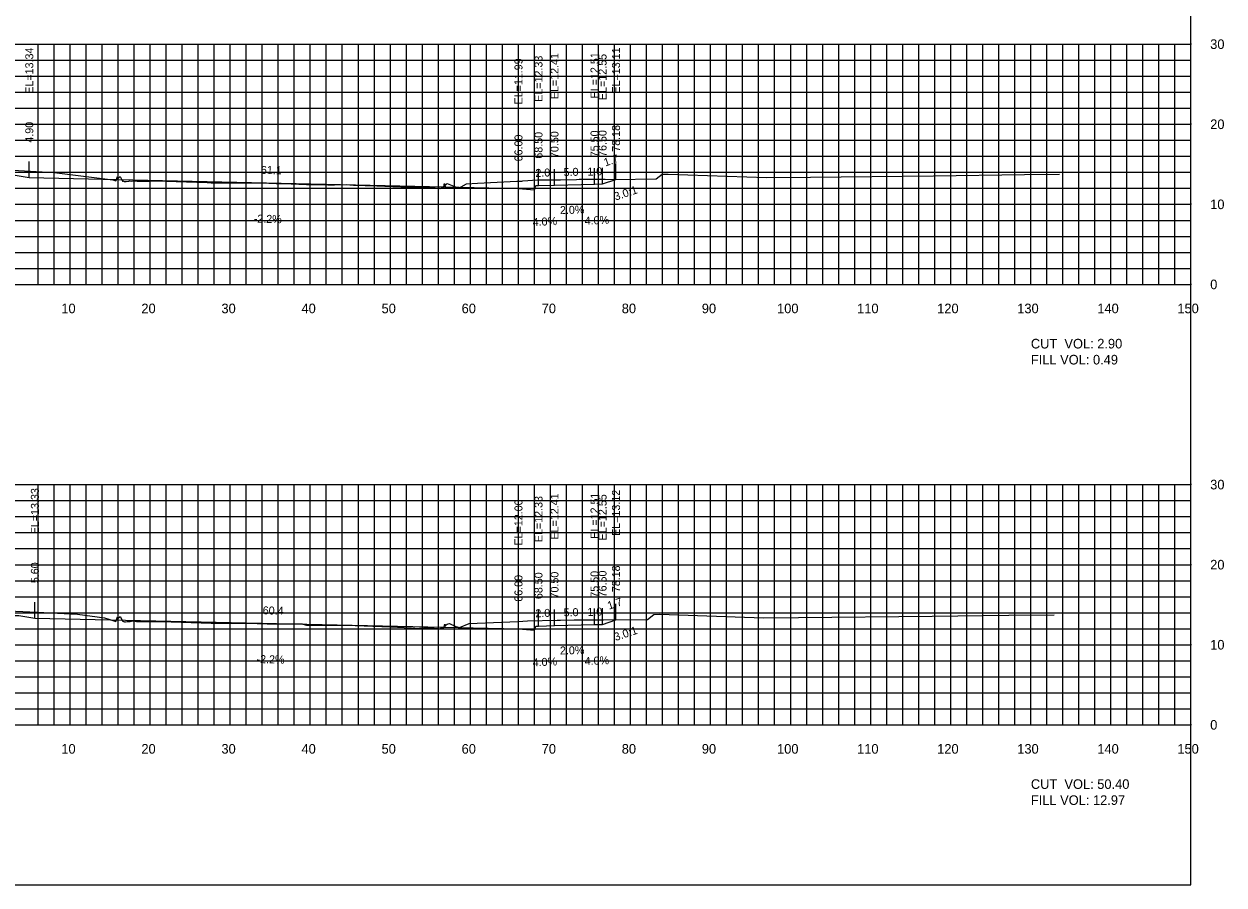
# Model space of a CAD drawing. Extents: x 1797419 to 1809236, y 248759 to 251512.
# Drawn here: x 1802635.2 to 1802785.1, y 250854.9 to 250962.4 of the extents above; entities that cross this region are included whole.
import ezdxf

# ---------------------------------------------------------------- set-up
doc = ezdxf.new("R2010")
doc.units = 0
for name, color, linetype in [('10', 7, 'Continuous'), ('3', 7, 'Continuous'), ('31', 7, 'Continuous'), ('4', 7, 'Continuous'), ('60', 7, 'Continuous'), ('ANNO-TXT', 7, 'Continuous'), ('CL-CNST', 7, 'Continuous'), ('Level 62', 7, 'Continuous'), ('M-ROADS', 7, 'Continuous')]:
    doc.layers.add(name, color=color, linetype=linetype)

msp = doc.modelspace()

# ---------------------------------------------------------------- linework, layer by layer
for p, q in [((1802635.9, 250943.23), (1802635.9, 250945.23)), ((1802697, 250941.88), (1802697, 250943.88)), ((1802699.5, 250942.22), (1802699.5, 250944.22)), ((1802701.5, 250942.3), (1802701.5, 250944.3)), ((1802706.5, 250942.4), (1802706.5, 250944.4)), ((1802707.5, 250942.44), (1802707.5, 250944.44)), ((1802709.18, 250943), (1802709.18, 250945)), ((1802636.6, 250888.22), (1802636.6, 250890.22)), ((1802709.18, 250888.01), (1802709.18, 250890.01)), ((1802697, 250886.89), (1802697, 250888.89)), ((1802699.5, 250887.22), (1802699.5, 250889.22)), ((1802701.5, 250887.3), (1802701.5, 250889.3)), ((1802706.5, 250887.4), (1802706.5, 250889.4)), ((1802707.5, 250887.44), (1802707.5, 250889.44))]:
    msp.add_line(p, q)
msp.add_lwpolyline([(1802481, 250854.89), (1802781, 250854.89), (1802781, 251044.89), (1802481, 251044.89)], close=True)
at = {"layer": '60'}
for p, q in [((1802781, 250929.89), (1802781, 250959.89)), ((1802781.06, 250959.89), (1802781, 250959.89)), ((1802781.06, 250949.89), (1802781, 250949.89)), ((1802781.06, 250939.89), (1802781, 250939.89)), ((1802481, 250929.89), (1802781, 250929.89)), ((1802641, 250929.83), (1802641, 250929.89)), ((1802651, 250929.83), (1802651, 250929.89)), ((1802661, 250929.83), (1802661, 250929.89)), ((1802671, 250929.83), (1802671, 250929.89)), ((1802681, 250929.83), (1802681, 250929.89)), ((1802691, 250929.83), (1802691, 250929.89)), ((1802701, 250929.83), (1802701, 250929.89)), ((1802711, 250929.83), (1802711, 250929.89)), ((1802721, 250929.83), (1802721, 250929.89)), ((1802731, 250929.83), (1802731, 250929.89)), ((1802741, 250929.83), (1802741, 250929.89)), ((1802751, 250929.83), (1802751, 250929.89)), ((1802761, 250929.83), (1802761, 250929.89)), ((1802771, 250929.83), (1802771, 250929.89)), ((1802781, 250929.83), (1802781, 250929.89)), ((1802781.06, 250929.89), (1802781, 250929.89)), ((1802781, 250874.89), (1802781, 250904.89)), ((1802781.06, 250904.89), (1802781, 250904.89)), ((1802781.06, 250894.89), (1802781, 250894.89)), ((1802781.06, 250884.89), (1802781, 250884.89)), ((1802481, 250874.89), (1802781, 250874.89)), ((1802641, 250874.83), (1802641, 250874.89)), ((1802651, 250874.83), (1802651, 250874.89)), ((1802661, 250874.83), (1802661, 250874.89)), ((1802671, 250874.83), (1802671, 250874.89)), ((1802681, 250874.83), (1802681, 250874.89)), ((1802691, 250874.83), (1802691, 250874.89)), ((1802701, 250874.83), (1802701, 250874.89)), ((1802711, 250874.83), (1802711, 250874.89)), ((1802721, 250874.83), (1802721, 250874.89)), ((1802731, 250874.83), (1802731, 250874.89)), ((1802741, 250874.83), (1802741, 250874.89)), ((1802751, 250874.83), (1802751, 250874.89)), ((1802761, 250874.83), (1802761, 250874.89)), ((1802771, 250874.83), (1802771, 250874.89)), ((1802781, 250874.83), (1802781, 250874.89)), ((1802781.06, 250874.89), (1802781, 250874.89))]:
    msp.add_line(p, q, dxfattribs=at)
at = {"layer": 'CL-CNST'}
for points in [[(1802563.49, 250943.08), (1802564.5, 250942.74), (1802565.5, 250942.7), (1802572.5, 250942.56), (1802574.5, 250942.48), (1802574.83, 250942.48), (1802575, 250941.98), (1802577, 250942.15), (1802621.76, 250943.13), (1802623.76, 250943.47), (1802624.26, 250943.47), (1802631, 250943.74), (1802633.4, 250943.57), (1802633.9, 250943.57), (1802635.9, 250943.23), (1802697, 250941.88), (1802699, 250941.72), (1802699.17, 250942.22), (1802699.5, 250942.22), (1802701.5, 250942.3), (1802706.5, 250942.4), (1802707.5, 250942.44), (1802709.18, 250943)], [(1802563.47, 250888.09), (1802564.5, 250887.75), (1802565.5, 250887.71), (1802572.5, 250887.57), (1802574.5, 250887.49), (1802574.83, 250887.49), (1802575, 250886.99), (1802577, 250887.15), (1802621.13, 250888.12), (1802623.13, 250888.46), (1802623.63, 250888.46), (1802631, 250888.76), (1802634.1, 250888.56), (1802634.6, 250888.56), (1802636.6, 250888.22), (1802697, 250886.89), (1802699, 250886.72), (1802699.17, 250887.22), (1802699.5, 250887.22), (1802701.5, 250887.3), (1802706.5, 250887.4), (1802707.5, 250887.44), (1802709.18, 250888.01)]]:
    msp.add_lwpolyline(points, dxfattribs=at)
at = {"layer": 'Level 62'}
for p, q in [((1802481, 250959.89), (1802781, 250959.89)), ((1802637, 250929.89), (1802637, 250959.89)), ((1802639, 250929.89), (1802639, 250959.89)), ((1802641, 250929.89), (1802641, 250959.89)), ((1802643, 250929.89), (1802643, 250959.89)), ((1802645, 250929.89), (1802645, 250959.89)), ((1802647, 250929.89), (1802647, 250959.89)), ((1802649, 250929.89), (1802649, 250959.89)), ((1802651, 250929.89), (1802651, 250959.89)), ((1802653, 250929.89), (1802653, 250959.89)), ((1802655, 250929.89), (1802655, 250959.89)), ((1802657, 250929.89), (1802657, 250959.89)), ((1802659, 250929.89), (1802659, 250959.89)), ((1802661, 250929.89), (1802661, 250959.89)), ((1802663, 250929.89), (1802663, 250959.89)), ((1802665, 250929.89), (1802665, 250959.89)), ((1802667, 250929.89), (1802667, 250959.89)), ((1802669, 250929.89), (1802669, 250959.89)), ((1802671, 250929.89), (1802671, 250959.89)), ((1802673, 250929.89), (1802673, 250959.89)), ((1802675, 250929.89), (1802675, 250959.89)), ((1802677, 250929.89), (1802677, 250959.89)), ((1802679, 250929.89), (1802679, 250959.89)), ((1802681, 250929.89), (1802681, 250959.89)), ((1802683, 250929.89), (1802683, 250959.89)), ((1802685, 250929.89), (1802685, 250959.89)), ((1802687, 250929.89), (1802687, 250959.89)), ((1802689, 250929.89), (1802689, 250959.89)), ((1802691, 250929.89), (1802691, 250959.89)), ((1802693, 250929.89), (1802693, 250959.89)), ((1802695, 250929.89), (1802695, 250959.89)), ((1802697, 250929.89), (1802697, 250959.89)), ((1802699, 250929.89), (1802699, 250959.89)), ((1802701, 250929.89), (1802701, 250959.89)), ((1802703, 250929.89), (1802703, 250959.89)), ((1802705, 250929.89), (1802705, 250959.89)), ((1802707, 250929.89), (1802707, 250959.89)), ((1802709, 250929.89), (1802709, 250959.89)), ((1802711, 250929.89), (1802711, 250959.89)), ((1802713, 250929.89), (1802713, 250959.89)), ((1802715, 250929.89), (1802715, 250959.89)), ((1802717, 250929.89), (1802717, 250959.89)), ((1802719, 250929.89), (1802719, 250959.89)), ((1802721, 250929.89), (1802721, 250959.89)), ((1802723, 250929.89), (1802723, 250959.89)), ((1802725, 250929.89), (1802725, 250959.89)), ((1802727, 250929.89), (1802727, 250959.89)), ((1802729, 250929.89), (1802729, 250959.89)), ((1802731, 250929.89), (1802731, 250959.89)), ((1802733, 250929.89), (1802733, 250959.89)), ((1802735, 250929.89), (1802735, 250959.89)), ((1802737, 250929.89), (1802737, 250959.89)), ((1802739, 250929.89), (1802739, 250959.89)), ((1802741, 250929.89), (1802741, 250959.89)), ((1802743, 250929.89), (1802743, 250959.89)), ((1802745, 250929.89), (1802745, 250959.89)), ((1802747, 250929.89), (1802747, 250959.89)), ((1802749, 250929.89), (1802749, 250959.89)), ((1802751, 250929.89), (1802751, 250959.89)), ((1802753, 250929.89), (1802753, 250959.89)), ((1802755, 250929.89), (1802755, 250959.89)), ((1802757, 250929.89), (1802757, 250959.89)), ((1802759, 250929.89), (1802759, 250959.89)), ((1802761, 250929.89), (1802761, 250959.89)), ((1802763, 250929.89), (1802763, 250959.89)), ((1802765, 250929.89), (1802765, 250959.89)), ((1802767, 250929.89), (1802767, 250959.89)), ((1802769, 250929.89), (1802769, 250959.89)), ((1802771, 250929.89), (1802771, 250959.89)), ((1802773, 250929.89), (1802773, 250959.89)), ((1802775, 250929.89), (1802775, 250959.89)), ((1802777, 250929.89), (1802777, 250959.89)), ((1802779, 250929.89), (1802779, 250959.89)), ((1802781, 250929.89), (1802781, 250959.89)), ((1802481, 250957.89), (1802781, 250957.89)), ((1802481, 250955.89), (1802781, 250955.89)), ((1802481, 250953.89), (1802781, 250953.89)), ((1802481, 250951.89), (1802781, 250951.89)), ((1802481, 250949.89), (1802781, 250949.89)), ((1802481, 250947.89), (1802781, 250947.89)), ((1802481, 250945.89), (1802781, 250945.89)), ((1802481, 250943.89), (1802781, 250943.89)), ((1802481, 250941.89), (1802781, 250941.89)), ((1802481, 250939.89), (1802781, 250939.89)), ((1802481, 250937.89), (1802781, 250937.89)), ((1802481, 250935.89), (1802781, 250935.89)), ((1802481, 250933.89), (1802781, 250933.89)), ((1802481, 250931.89), (1802781, 250931.89)), ((1802481, 250929.89), (1802781, 250929.89)), ((1802481, 250904.89), (1802781, 250904.89)), ((1802637, 250874.89), (1802637, 250904.89)), ((1802639, 250874.89), (1802639, 250904.89)), ((1802641, 250874.89), (1802641, 250904.89)), ((1802643, 250874.89), (1802643, 250904.89)), ((1802645, 250874.89), (1802645, 250904.89)), ((1802647, 250874.89), (1802647, 250904.89)), ((1802649, 250874.89), (1802649, 250904.89)), ((1802651, 250874.89), (1802651, 250904.89)), ((1802653, 250874.89), (1802653, 250904.89)), ((1802655, 250874.89), (1802655, 250904.89)), ((1802657, 250874.89), (1802657, 250904.89)), ((1802659, 250874.89), (1802659, 250904.89)), ((1802661, 250874.89), (1802661, 250904.89)), ((1802663, 250874.89), (1802663, 250904.89)), ((1802665, 250874.89), (1802665, 250904.89)), ((1802667, 250874.89), (1802667, 250904.89)), ((1802669, 250874.89), (1802669, 250904.89)), ((1802671, 250874.89), (1802671, 250904.89)), ((1802673, 250874.89), (1802673, 250904.89)), ((1802675, 250874.89), (1802675, 250904.89)), ((1802677, 250874.89), (1802677, 250904.89)), ((1802679, 250874.89), (1802679, 250904.89)), ((1802681, 250874.89), (1802681, 250904.89)), ((1802683, 250874.89), (1802683, 250904.89)), ((1802685, 250874.89), (1802685, 250904.89)), ((1802687, 250874.89), (1802687, 250904.89)), ((1802689, 250874.89), (1802689, 250904.89)), ((1802691, 250874.89), (1802691, 250904.89)), ((1802693, 250874.89), (1802693, 250904.89)), ((1802695, 250874.89), (1802695, 250904.89)), ((1802697, 250874.89), (1802697, 250904.89)), ((1802699, 250874.89), (1802699, 250904.89)), ((1802701, 250874.89), (1802701, 250904.89)), ((1802703, 250874.89), (1802703, 250904.89)), ((1802705, 250874.89), (1802705, 250904.89)), ((1802707, 250874.89), (1802707, 250904.89)), ((1802709, 250874.89), (1802709, 250904.89)), ((1802711, 250874.89), (1802711, 250904.89)), ((1802713, 250874.89), (1802713, 250904.89)), ((1802715, 250874.89), (1802715, 250904.89)), ((1802717, 250874.89), (1802717, 250904.89)), ((1802719, 250874.89), (1802719, 250904.89)), ((1802721, 250874.89), (1802721, 250904.89)), ((1802723, 250874.89), (1802723, 250904.89)), ((1802725, 250874.89), (1802725, 250904.89)), ((1802727, 250874.89), (1802727, 250904.89)), ((1802729, 250874.89), (1802729, 250904.89)), ((1802731, 250874.89), (1802731, 250904.89)), ((1802733, 250874.89), (1802733, 250904.89)), ((1802735, 250874.89), (1802735, 250904.89)), ((1802737, 250874.89), (1802737, 250904.89)), ((1802739, 250874.89), (1802739, 250904.89)), ((1802741, 250874.89), (1802741, 250904.89)), ((1802743, 250874.89), (1802743, 250904.89)), ((1802745, 250874.89), (1802745, 250904.89)), ((1802747, 250874.89), (1802747, 250904.89)), ((1802749, 250874.89), (1802749, 250904.89)), ((1802751, 250874.89), (1802751, 250904.89)), ((1802753, 250874.89), (1802753, 250904.89)), ((1802755, 250874.89), (1802755, 250904.89)), ((1802757, 250874.89), (1802757, 250904.89)), ((1802759, 250874.89), (1802759, 250904.89)), ((1802761, 250874.89), (1802761, 250904.89)), ((1802763, 250874.89), (1802763, 250904.89)), ((1802765, 250874.89), (1802765, 250904.89)), ((1802767, 250874.89), (1802767, 250904.89)), ((1802769, 250874.89), (1802769, 250904.89)), ((1802771, 250874.89), (1802771, 250904.89)), ((1802773, 250874.89), (1802773, 250904.89)), ((1802775, 250874.89), (1802775, 250904.89)), ((1802777, 250874.89), (1802777, 250904.89)), ((1802779, 250874.89), (1802779, 250904.89)), ((1802781, 250874.89), (1802781, 250904.89)), ((1802481, 250902.89), (1802781, 250902.89)), ((1802481, 250900.89), (1802781, 250900.89)), ((1802481, 250898.89), (1802781, 250898.89)), ((1802481, 250896.89), (1802781, 250896.89)), ((1802481, 250894.89), (1802781, 250894.89)), ((1802481, 250892.89), (1802781, 250892.89)), ((1802481, 250890.89), (1802781, 250890.89)), ((1802481, 250888.89), (1802781, 250888.89)), ((1802481, 250886.89), (1802781, 250886.89)), ((1802481, 250884.89), (1802781, 250884.89)), ((1802481, 250882.89), (1802781, 250882.89)), ((1802481, 250880.89), (1802781, 250880.89)), ((1802481, 250878.89), (1802781, 250878.89)), ((1802481, 250876.89), (1802781, 250876.89)), ((1802481, 250874.89), (1802781, 250874.89))]:
    msp.add_line(p, q, dxfattribs=at)
at = {"layer": 'M-ROADS'}
for points in [[(1802630.05, 250944.35), (1802639.01, 250943.86), (1802646.33, 250942.95), (1802646.71, 250942.82), (1802646.74, 250942.86), (1802646.92, 250943.38), (1802646.94, 250943.3), (1802646.94, 250943.32), (1802647.05, 250943.16), (1802647.25, 250943.37), (1802647.55, 250942.78), (1802647.59, 250942.78), (1802647.63, 250942.81), (1802647.64, 250942.79), (1802647.64, 250942.81), (1802647.66, 250942.79), (1802647.76, 250942.75), (1802647.87, 250942.75), (1802648.01, 250942.74), (1802648.33, 250942.8), (1802648.45, 250942.82), (1802648.62, 250942.8), (1802648.85, 250942.81), (1802648.92, 250942.81), (1802649.04, 250942.81), (1802649.36, 250942.8), (1802650.88, 250942.8), (1802651.67, 250942.81), (1802658.12, 250942.61), (1802658.61, 250942.59), (1802658.91, 250942.59), (1802659.45, 250942.59), (1802661.03, 250942.59), (1802661.25, 250942.59), (1802662.09, 250942.59), (1802663.56, 250942.59), (1802665.84, 250942.53), (1802666.72, 250942.5), (1802667.4, 250942.48), (1802667.64, 250942.47), (1802670.54, 250942.35), (1802670.83, 250942.35), (1802671.34, 250942.35), (1802672.96, 250942.35), (1802673.19, 250942.34), (1802674.01, 250942.34), (1802675.49, 250942.35), (1802676.38, 250942.3), (1802679.3, 250942.18), (1802682.32, 250942.07), (1802682.73, 250942.05), (1802682.99, 250942.05), (1802683.45, 250942.05), (1802685.15, 250942.05), (1802685.39, 250942.04), (1802686.1, 250941.99), (1802686.61, 250941.93), (1802686.87, 250941.9), (1802687.07, 250941.9), (1802687.17, 250941.87), (1802687.19, 250941.84), (1802687.2, 250941.88), (1802687.2, 250941.87), (1802687.2, 250941.87), (1802687.21, 250941.89), (1802687.24, 250941.91), (1802687.28, 250941.98), (1802687.31, 250941.92), (1802687.47, 250941.99), (1802687.53, 250942), (1802687.63, 250942.04), (1802687.65, 250942.03), (1802687.68, 250942.05), (1802687.72, 250942.31), (1802687.74, 250942.4), (1802687.76, 250942.48), (1802687.84, 250942.12), (1802687.85, 250942.36), (1802687.87, 250942.34), (1802687.9, 250942.37), (1802687.97, 250942.35), (1802688.11, 250942.47), (1802688.3, 250942.42), (1802689.57, 250941.9), (1802690.53, 250942.44), (1802691.89, 250942.55), (1802696.81, 250942.77), (1802697.42, 250942.8), (1802697.53, 250942.81), (1802699.37, 250942.95), (1802699.42, 250942.95), (1802701.91, 250942.95), (1802702.25, 250942.96), (1802704.26, 250942.97), (1802704.6, 250943.03), (1802705.28, 250943.03), (1802707, 250943.02), (1802707.83, 250943.02), (1802709, 250943), (1802714.22, 250943.06), (1802714.96, 250943.64), (1802715.69, 250943.67), (1802727.97, 250943.25), (1802733.46, 250943.3), (1802748.85, 250943.45), (1802760.21, 250943.6), (1802764.56, 250943.64)], [(1802633.31, 250889.13), (1802636.88, 250888.96), (1802641.93, 250888.69), (1802645.28, 250888.27), (1802645.83, 250888.08), (1802646.73, 250887.81), (1802646.75, 250887.87), (1802646.92, 250888.38), (1802646.94, 250888.31), (1802646.94, 250888.33), (1802647.02, 250888.21), (1802647.24, 250888.43), (1802647.57, 250887.79), (1802647.6, 250887.79), (1802647.64, 250887.82), (1802647.64, 250887.81), (1802647.65, 250887.83), (1802647.66, 250887.81), (1802647.78, 250887.77), (1802647.85, 250887.76), (1802647.93, 250887.76), (1802648.13, 250887.8), (1802648.21, 250887.81), (1802648.32, 250887.79), (1802648.49, 250887.8), (1802648.85, 250887.87), (1802648.88, 250887.87), (1802648.95, 250887.86), (1802649.29, 250887.81), (1802651.63, 250887.81), (1802651.69, 250887.81), (1802652.39, 250887.79), (1802658.61, 250887.59), (1802659.13, 250887.59), (1802660.94, 250887.6), (1802661.34, 250887.59), (1802661.41, 250887.59), (1802661.7, 250887.59), (1802663.56, 250887.6), (1802664.37, 250887.53), (1802665.6, 250887.49), (1802667.42, 250887.49), (1802669.86, 250887.49), (1802669.98, 250887.49), (1802670.08, 250887.46), (1802670.54, 250887.34), (1802671.09, 250887.34), (1802672.86, 250887.35), (1802673.27, 250887.35), (1802673.34, 250887.35), (1802673.64, 250887.35), (1802675.49, 250887.34), (1802681.06, 250887.13), (1802682.73, 250887.06), (1802683.64, 250887), (1802684.47, 250886.93), (1802684.64, 250886.97), (1802685.13, 250887.01), (1802685.45, 250887.05), (1802685.53, 250887.05), (1802685.69, 250887.03), (1802686.89, 250886.94), (1802686.97, 250886.89), (1802687.09, 250886.89), (1802687.18, 250886.87), (1802687.19, 250886.85), (1802687.2, 250886.9), (1802687.21, 250886.89), (1802687.21, 250886.89), (1802687.21, 250886.9), (1802687.24, 250886.92), (1802687.26, 250886.96), (1802687.28, 250886.93), (1802687.36, 250886.96), (1802687.39, 250886.97), (1802687.44, 250886.99), (1802687.51, 250886.95), (1802687.58, 250886.99), (1802687.68, 250887.06), (1802687.7, 250887.16), (1802687.79, 250887.47), (1802687.85, 250887.19), (1802687.86, 250887.37), (1802687.87, 250887.36), (1802687.9, 250887.38), (1802687.95, 250887.37), (1802688.09, 250887.48), (1802688.23, 250887.49), (1802688.4, 250887.55), (1802689.17, 250887.15), (1802689.65, 250887.03), (1802690.86, 250887.53), (1802694.9, 250887.72), (1802696.95, 250887.78), (1802698.13, 250887.87), (1802701.82, 250887.94), (1802702.26, 250887.95), (1802703.95, 250888.02), (1802705.51, 250888.01), (1802706.39, 250888.01), (1802707.61, 250887.99), (1802713.11, 250888.05), (1802713.9, 250888.67), (1802714.67, 250888.69), (1802727.59, 250888.25), (1802731.97, 250888.29), (1802748.69, 250888.45), (1802758.24, 250888.58), (1802763.93, 250888.64)]]:
    msp.add_lwpolyline(points, dxfattribs=at)

# ---------------------------------------------------------------- texts
for p in [(1802709.13, 250940.35), (1802709.13, 250885.35)]:
    msp.add_text('3.0:1', height=1, rotation=18.4349).set_placement(p)
at = {"layer": '10'}
for s, p in [('10', (1802639.9, 250926.29)), ('20', (1802649.9, 250926.29)), ('30', (1802659.9, 250926.29)), ('40', (1802669.9, 250926.29)), ('50', (1802679.9, 250926.29)), ('60', (1802689.9, 250926.29)), ('70', (1802699.9, 250926.29)), ('80', (1802709.9, 250926.29)), ('90', (1802719.9, 250926.29)), ('100', (1802729.3, 250926.29)), ('110', (1802739.3, 250926.29)), ('120', (1802749.3, 250926.29)), ('130', (1802759.3, 250926.29)), ('140', (1802769.3, 250926.29)), ('150', (1802779.3, 250926.29)), ('10', (1802639.9, 250871.29)), ('20', (1802649.9, 250871.29)), ('30', (1802659.9, 250871.29)), ('40', (1802669.9, 250871.29)), ('50', (1802679.9, 250871.29)), ('60', (1802689.9, 250871.29)), ('70', (1802699.9, 250871.29)), ('80', (1802709.9, 250871.29)), ('90', (1802719.9, 250871.29)), ('100', (1802729.3, 250871.29)), ('110', (1802739.3, 250871.29)), ('120', (1802749.3, 250871.29)), ('130', (1802759.3, 250871.29)), ('140', (1802769.3, 250871.29)), ('150', (1802779.3, 250871.29))]:
    msp.add_text(s, height=1.2, dxfattribs=at).set_placement(p)
at = {"layer": '3'}
for s, p in [('EL=13.34', (1802636.4, 250953.7)), ('EL=12.41', (1802702, 250953.02)), ('EL=12.51', (1802707, 250953.12)), ('EL=12.55', (1802708, 250952.91)), ('EL=13.11', (1802709.68, 250953.72)), ('EL=11.99', (1802697.5, 250952.36)), ('EL=12.33', (1802700, 250952.69)), ('4.90', (1802636.4, 250947.59)), ('78.18', (1802709.68, 250946.45)), ('66.00', (1802697.5, 250945.25)), ('68.50', (1802700, 250945.59)), ('70.50', (1802702, 250945.67)), ('75.50', (1802707, 250945.77)), ('76.50', (1802708, 250945.81)), ('EL=13.33', (1802637.1, 250898.69)), ('EL=12.33', (1802700, 250897.7)), ('EL=12.41', (1802702, 250898.03)), ('EL=12.51', (1802707, 250898.13)), ('EL=12.55', (1802708, 250897.92)), ('EL=13.12', (1802709.68, 250898.48)), ('EL=12.00', (1802697.5, 250897.28)), ('5.60', (1802637.1, 250892.58)), ('75.50', (1802707, 250890.77)), ('76.50', (1802708, 250890.81)), ('78.18', (1802709.68, 250891.45)), ('66.00', (1802697.5, 250890.26)), ('68.50', (1802700, 250890.59)), ('70.50', (1802702, 250890.67))]:
    msp.add_text(s, height=1, rotation=90, dxfattribs=at).set_placement(p)
at = {"layer": '31'}
for s, p in [('30', (1802783.4, 250959.29)), ('20', (1802783.4, 250949.29)), ('10', (1802783.4, 250939.29)), ('0', (1802783.4, 250929.29)), ('30', (1802783.4, 250904.29)), ('20', (1802783.4, 250894.29)), ('10', (1802783.4, 250884.29)), ('0', (1802783.4, 250874.29))]:
    msp.add_text(s, height=1.2, dxfattribs=at).set_placement(p)
at = {"layer": '4'}
for s, rotation, p in [('1.7', 18.4349, (1802707.85, 250944.61)), ('61.1', 358.7397, (1802664.82, 250943.69)), ('2.0', 2.2906, (1802699.13, 250943.3)), ('5.0', 1.1458, (1802702.65, 250943.42)), ('1.0', 2.2906, (1802705.63, 250943.46)), ('2.0%', 1.1458, (1802702.19, 250938.67)), ('-2.2%', 358.7397, (1802663.93, 250937.61)), ('4.0%', 2.2906, (1802698.79, 250937.18)), ('4.0%', 2.2906, (1802705.29, 250937.34)), ('60.4', 358.7397, (1802665.05, 250888.69)), ('1.7', 18.4349, (1802708.3, 250889.26)), ('2.0', 2.2906, (1802699.13, 250888.31)), ('5.0', 1.1458, (1802702.65, 250888.43)), ('1.0', 2.2906, (1802705.63, 250888.47)), ('-2.2%', 358.7397, (1802664.28, 250882.61)), ('2.0%', 1.1458, (1802702.19, 250883.67)), ('4.0%', 2.2906, (1802698.79, 250882.19)), ('4.0%', 2.2906, (1802705.29, 250882.35))]:
    msp.add_text(s, height=1, rotation=rotation, dxfattribs=at).set_placement(p)
at = {"layer": 'ANNO-TXT'}
for s, p in [('CUT  VOL: 2.90', (1802761, 250921.89)), ('FILL VOL: 0.49', (1802761, 250919.89)), ('CUT  VOL: 50.40', (1802761, 250866.89)), ('FILL VOL: 12.97', (1802761, 250864.89))]:
    msp.add_text(s, height=1.2, dxfattribs=at).set_placement(p)

doc.saveas('drawing.dxf')
